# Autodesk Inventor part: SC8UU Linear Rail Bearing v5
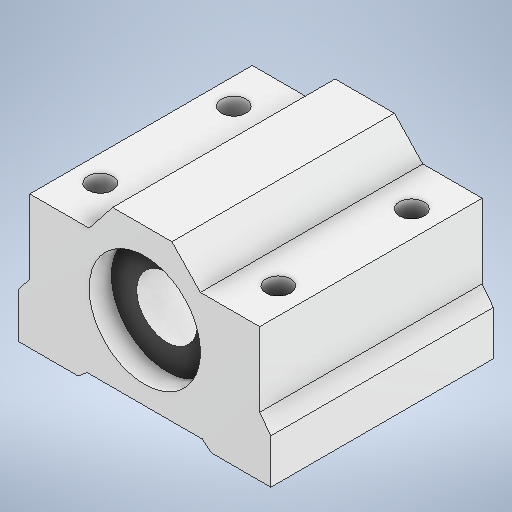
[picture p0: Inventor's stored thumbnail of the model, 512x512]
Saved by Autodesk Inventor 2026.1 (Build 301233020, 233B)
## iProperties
Created: 2021-02
Part Number: SC8UU Linear Rail Bearing v5
Material: Aluminum
Document SubType Name: Modeling
Designer: hp
Density: 2.7 g/cm^3
Appearance: Default
Title: H:/Downloads/SC8UU Linear Rail Bearing v5.step
Sending System: Autodesk Translation Framework v9.7.1.1290
Preprocessor: ST-DEVELOPER v18.1
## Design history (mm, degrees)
feature "Body1"
body "Solid1"
